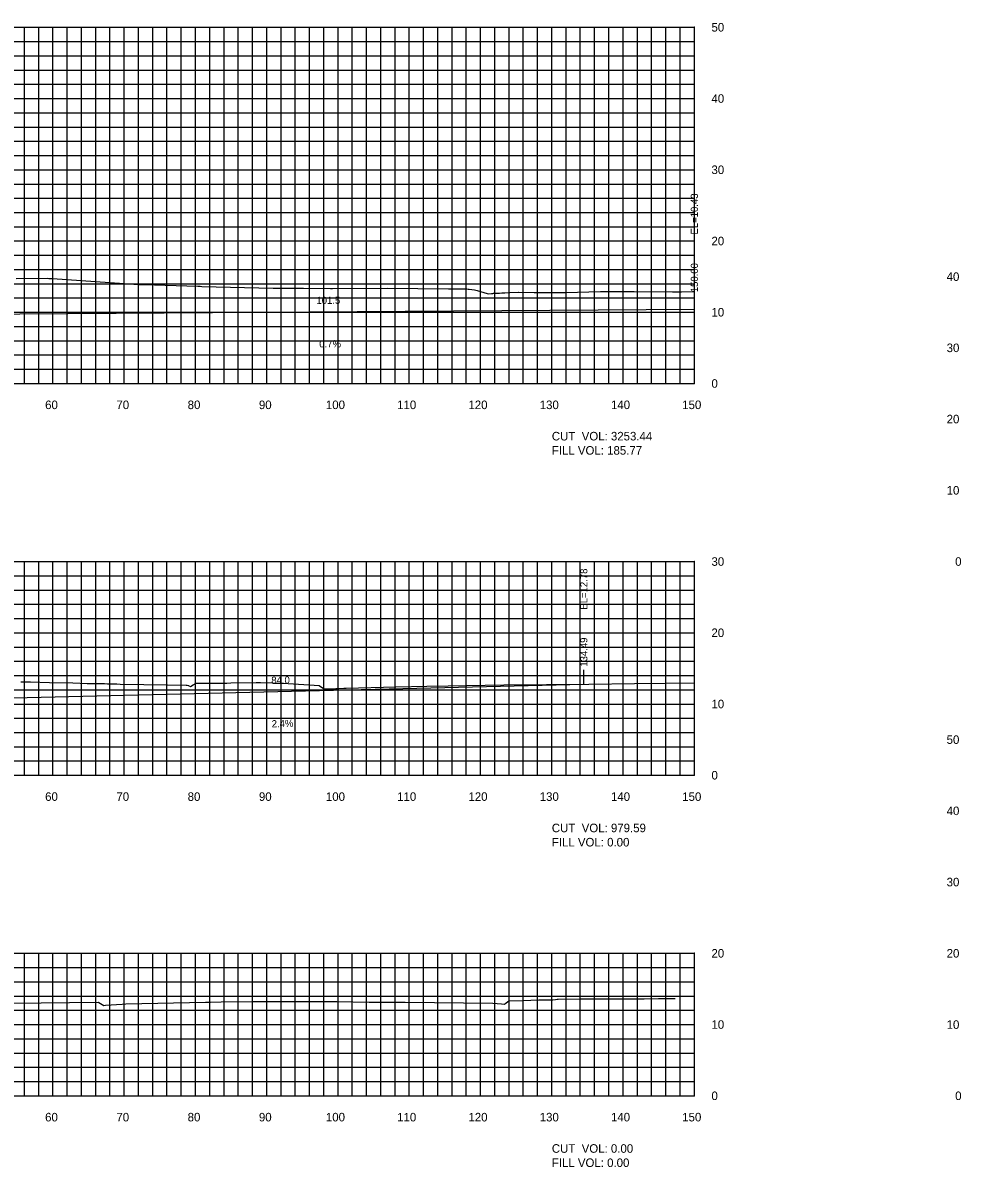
# Model space of a CAD drawing. Extents: x 1797789 to 1803805, y 249066 to 250293.
# Drawn here: x 1802346.8 to 1802478.4, y 250089.4 to 250250 of the extents above; entities that cross this region are included whole.
import ezdxf

# ---------------------------------------------------------------- set-up
doc = ezdxf.new("R2010")
doc.units = 0
for name, color, linetype in [('10', 7, 'Continuous'), ('3', 7, 'Continuous'), ('31', 7, 'Continuous'), ('4', 7, 'Continuous'), ('60', 7, 'Continuous'), ('ANNO-TXT', 7, 'Continuous'), ('CL-CNST', 7, 'Continuous'), ('Level 62', 7, 'Continuous'), ('M-ROADS', 7, 'Continuous')]:
    doc.layers.add(name, color=color, linetype=linetype)

msp = doc.modelspace()

# ---------------------------------------------------------------- linework, layer by layer
for p, q in [((1802441, 250209.87), (1802441, 250211.87)), ((1802425.49, 250157.21), (1802425.49, 250159.21))]:
    msp.add_line(p, q)
at = {"layer": '60'}
for p, q in [((1802441, 250199.43), (1802441, 250249.43)), ((1802441.06, 250249.43), (1802441, 250249.43)), ((1802441.06, 250239.43), (1802441, 250239.43)), ((1802441.06, 250229.43), (1802441, 250229.43)), ((1802441.06, 250219.43), (1802441, 250219.43)), ((1802441.06, 250209.43), (1802441, 250209.43)), ((1802141, 250199.43), (1802441, 250199.43)), ((1802351, 250199.37), (1802351, 250199.43)), ((1802361, 250199.37), (1802361, 250199.43)), ((1802371, 250199.37), (1802371, 250199.43)), ((1802381, 250199.37), (1802381, 250199.43)), ((1802391, 250199.37), (1802391, 250199.43)), ((1802401, 250199.37), (1802401, 250199.43)), ((1802411, 250199.37), (1802411, 250199.43)), ((1802421, 250199.37), (1802421, 250199.43)), ((1802431, 250199.37), (1802431, 250199.43)), ((1802441, 250199.37), (1802441, 250199.43)), ((1802441.06, 250199.43), (1802441, 250199.43)), ((1802441, 250144.43), (1802441, 250174.43)), ((1802441.06, 250174.43), (1802441, 250174.43)), ((1802441.06, 250164.43), (1802441, 250164.43)), ((1802441.06, 250154.43), (1802441, 250154.43)), ((1802141, 250144.43), (1802441, 250144.43)), ((1802351, 250144.37), (1802351, 250144.43)), ((1802361, 250144.37), (1802361, 250144.43)), ((1802371, 250144.37), (1802371, 250144.43)), ((1802381, 250144.37), (1802381, 250144.43)), ((1802391, 250144.37), (1802391, 250144.43)), ((1802401, 250144.37), (1802401, 250144.43)), ((1802411, 250144.37), (1802411, 250144.43)), ((1802421, 250144.37), (1802421, 250144.43)), ((1802431, 250144.37), (1802431, 250144.43)), ((1802441, 250144.37), (1802441, 250144.43)), ((1802441.06, 250144.43), (1802441, 250144.43)), ((1802441, 250099.43), (1802441, 250119.43)), ((1802441.06, 250119.43), (1802441, 250119.43)), ((1802441.06, 250109.43), (1802441, 250109.43)), ((1802141, 250099.43), (1802441, 250099.43)), ((1802351, 250099.37), (1802351, 250099.43)), ((1802361, 250099.37), (1802361, 250099.43)), ((1802371, 250099.37), (1802371, 250099.43)), ((1802381, 250099.37), (1802381, 250099.43)), ((1802391, 250099.37), (1802391, 250099.43)), ((1802401, 250099.37), (1802401, 250099.43)), ((1802411, 250099.37), (1802411, 250099.43)), ((1802421, 250099.37), (1802421, 250099.43)), ((1802431, 250099.37), (1802431, 250099.43)), ((1802441, 250099.37), (1802441, 250099.43)), ((1802441.06, 250099.43), (1802441, 250099.43))]:
    msp.add_line(p, q, dxfattribs=at)
at = {"layer": 'CL-CNST'}
for points in [[(1802182.07, 250229.29), (1802242.5, 250209.15), (1802243.5, 250209.11), (1802250.5, 250209), (1802250.5, 250209), (1802250.83, 250209), (1802251, 250208.5), (1802253, 250208.66), (1802257, 250208.75), (1802291, 250209.5), (1802325, 250208.75), (1802329, 250208.66), (1802331, 250208.5), (1802331.17, 250209), (1802331.5, 250209), (1802331.5, 250209), (1802338.5, 250209.11), (1802339.5, 250209.15), (1802441, 250209.87)], [(1802236.11, 250157.24), (1802242.5, 250155.11), (1802243.5, 250155.07), (1802250.5, 250154.96), (1802250.5, 250154.96), (1802250.83, 250154.96), (1802251, 250154.46), (1802253, 250154.62), (1802257, 250154.71), (1802291, 250155.46), (1802325, 250154.71), (1802329, 250154.62), (1802331, 250154.46), (1802331.17, 250154.96), (1802331.5, 250154.96), (1802333.5, 250155.04), (1802340.5, 250155.15), (1802341.5, 250155.19), (1802425.49, 250157.21)]]:
    msp.add_lwpolyline(points, dxfattribs=at)
at = {"layer": 'Level 62'}
for p, q in [((1802141, 250249.43), (1802441, 250249.43)), ((1802347, 250199.43), (1802347, 250249.43)), ((1802349, 250199.43), (1802349, 250249.43)), ((1802351, 250199.43), (1802351, 250249.43)), ((1802353, 250199.43), (1802353, 250249.43)), ((1802355, 250199.43), (1802355, 250249.43)), ((1802357, 250199.43), (1802357, 250249.43)), ((1802359, 250199.43), (1802359, 250249.43)), ((1802361, 250199.43), (1802361, 250249.43)), ((1802363, 250199.43), (1802363, 250249.43)), ((1802365, 250199.43), (1802365, 250249.43)), ((1802367, 250199.43), (1802367, 250249.43)), ((1802369, 250199.43), (1802369, 250249.43)), ((1802371, 250199.43), (1802371, 250249.43)), ((1802373, 250199.43), (1802373, 250249.43)), ((1802375, 250199.43), (1802375, 250249.43)), ((1802377, 250199.43), (1802377, 250249.43)), ((1802379, 250199.43), (1802379, 250249.43)), ((1802381, 250199.43), (1802381, 250249.43)), ((1802383, 250199.43), (1802383, 250249.43)), ((1802385, 250199.43), (1802385, 250249.43)), ((1802387, 250199.43), (1802387, 250249.43)), ((1802389, 250199.43), (1802389, 250249.43)), ((1802391, 250199.43), (1802391, 250249.43)), ((1802393, 250199.43), (1802393, 250249.43)), ((1802395, 250199.43), (1802395, 250249.43)), ((1802397, 250199.43), (1802397, 250249.43)), ((1802399, 250199.43), (1802399, 250249.43)), ((1802401, 250199.43), (1802401, 250249.43)), ((1802403, 250199.43), (1802403, 250249.43)), ((1802405, 250199.43), (1802405, 250249.43)), ((1802407, 250199.43), (1802407, 250249.43)), ((1802409, 250199.43), (1802409, 250249.43)), ((1802411, 250199.43), (1802411, 250249.43)), ((1802413, 250199.43), (1802413, 250249.43)), ((1802415, 250199.43), (1802415, 250249.43)), ((1802417, 250199.43), (1802417, 250249.43)), ((1802419, 250199.43), (1802419, 250249.43)), ((1802421, 250199.43), (1802421, 250249.43)), ((1802423, 250199.43), (1802423, 250249.43)), ((1802425, 250199.43), (1802425, 250249.43)), ((1802427, 250199.43), (1802427, 250249.43)), ((1802429, 250199.43), (1802429, 250249.43)), ((1802431, 250199.43), (1802431, 250249.43)), ((1802433, 250199.43), (1802433, 250249.43)), ((1802435, 250199.43), (1802435, 250249.43)), ((1802437, 250199.43), (1802437, 250249.43)), ((1802439, 250199.43), (1802439, 250249.43)), ((1802441, 250199.43), (1802441, 250249.43)), ((1802141, 250247.43), (1802441, 250247.43)), ((1802141, 250245.43), (1802441, 250245.43)), ((1802141, 250243.43), (1802441, 250243.43)), ((1802141, 250241.43), (1802441, 250241.43)), ((1802141, 250239.43), (1802441, 250239.43)), ((1802141, 250237.43), (1802441, 250237.43)), ((1802141, 250235.43), (1802441, 250235.43)), ((1802141, 250233.43), (1802441, 250233.43)), ((1802141, 250231.43), (1802441, 250231.43)), ((1802141, 250229.43), (1802441, 250229.43)), ((1802141, 250227.43), (1802441, 250227.43)), ((1802141, 250225.43), (1802441, 250225.43)), ((1802141, 250223.43), (1802441, 250223.43)), ((1802141, 250221.43), (1802441, 250221.43)), ((1802141, 250219.43), (1802441, 250219.43)), ((1802141, 250217.43), (1802441, 250217.43)), ((1802141, 250215.43), (1802441, 250215.43)), ((1802141, 250213.43), (1802441, 250213.43)), ((1802141, 250211.43), (1802441, 250211.43)), ((1802141, 250209.43), (1802441, 250209.43)), ((1802141, 250207.43), (1802441, 250207.43)), ((1802141, 250205.43), (1802441, 250205.43)), ((1802141, 250203.43), (1802441, 250203.43)), ((1802141, 250201.43), (1802441, 250201.43)), ((1802141, 250199.43), (1802441, 250199.43)), ((1802141, 250174.43), (1802441, 250174.43)), ((1802347, 250144.43), (1802347, 250174.43)), ((1802349, 250144.43), (1802349, 250174.43)), ((1802351, 250144.43), (1802351, 250174.43)), ((1802353, 250144.43), (1802353, 250174.43)), ((1802355, 250144.43), (1802355, 250174.43)), ((1802357, 250144.43), (1802357, 250174.43)), ((1802359, 250144.43), (1802359, 250174.43)), ((1802361, 250144.43), (1802361, 250174.43)), ((1802363, 250144.43), (1802363, 250174.43)), ((1802365, 250144.43), (1802365, 250174.43)), ((1802367, 250144.43), (1802367, 250174.43)), ((1802369, 250144.43), (1802369, 250174.43)), ((1802371, 250144.43), (1802371, 250174.43)), ((1802373, 250144.43), (1802373, 250174.43)), ((1802375, 250144.43), (1802375, 250174.43)), ((1802377, 250144.43), (1802377, 250174.43)), ((1802379, 250144.43), (1802379, 250174.43)), ((1802381, 250144.43), (1802381, 250174.43)), ((1802383, 250144.43), (1802383, 250174.43)), ((1802385, 250144.43), (1802385, 250174.43)), ((1802387, 250144.43), (1802387, 250174.43)), ((1802389, 250144.43), (1802389, 250174.43)), ((1802391, 250144.43), (1802391, 250174.43)), ((1802393, 250144.43), (1802393, 250174.43)), ((1802395, 250144.43), (1802395, 250174.43)), ((1802397, 250144.43), (1802397, 250174.43)), ((1802399, 250144.43), (1802399, 250174.43)), ((1802401, 250144.43), (1802401, 250174.43)), ((1802403, 250144.43), (1802403, 250174.43)), ((1802405, 250144.43), (1802405, 250174.43)), ((1802407, 250144.43), (1802407, 250174.43)), ((1802409, 250144.43), (1802409, 250174.43)), ((1802411, 250144.43), (1802411, 250174.43)), ((1802413, 250144.43), (1802413, 250174.43)), ((1802415, 250144.43), (1802415, 250174.43)), ((1802417, 250144.43), (1802417, 250174.43)), ((1802419, 250144.43), (1802419, 250174.43)), ((1802421, 250144.43), (1802421, 250174.43)), ((1802423, 250144.43), (1802423, 250174.43)), ((1802425, 250144.43), (1802425, 250174.43)), ((1802427, 250144.43), (1802427, 250174.43)), ((1802429, 250144.43), (1802429, 250174.43)), ((1802431, 250144.43), (1802431, 250174.43)), ((1802433, 250144.43), (1802433, 250174.43)), ((1802435, 250144.43), (1802435, 250174.43)), ((1802437, 250144.43), (1802437, 250174.43)), ((1802439, 250144.43), (1802439, 250174.43)), ((1802441, 250144.43), (1802441, 250174.43)), ((1802141, 250172.43), (1802441, 250172.43)), ((1802141, 250170.43), (1802441, 250170.43)), ((1802141, 250168.43), (1802441, 250168.43)), ((1802141, 250166.43), (1802441, 250166.43)), ((1802141, 250164.43), (1802441, 250164.43)), ((1802141, 250162.43), (1802441, 250162.43)), ((1802141, 250160.43), (1802441, 250160.43)), ((1802141, 250158.43), (1802441, 250158.43)), ((1802141, 250156.43), (1802441, 250156.43)), ((1802141, 250154.43), (1802441, 250154.43)), ((1802141, 250152.43), (1802441, 250152.43)), ((1802141, 250150.43), (1802441, 250150.43)), ((1802141, 250148.43), (1802441, 250148.43)), ((1802141, 250146.43), (1802441, 250146.43)), ((1802141, 250144.43), (1802441, 250144.43)), ((1802141, 250119.43), (1802441, 250119.43)), ((1802347, 250099.43), (1802347, 250119.43)), ((1802349, 250099.43), (1802349, 250119.43)), ((1802351, 250099.43), (1802351, 250119.43)), ((1802353, 250099.43), (1802353, 250119.43)), ((1802355, 250099.43), (1802355, 250119.43)), ((1802357, 250099.43), (1802357, 250119.43)), ((1802359, 250099.43), (1802359, 250119.43)), ((1802361, 250099.43), (1802361, 250119.43)), ((1802363, 250099.43), (1802363, 250119.43)), ((1802365, 250099.43), (1802365, 250119.43)), ((1802367, 250099.43), (1802367, 250119.43)), ((1802369, 250099.43), (1802369, 250119.43)), ((1802371, 250099.43), (1802371, 250119.43)), ((1802373, 250099.43), (1802373, 250119.43)), ((1802375, 250099.43), (1802375, 250119.43)), ((1802377, 250099.43), (1802377, 250119.43)), ((1802379, 250099.43), (1802379, 250119.43)), ((1802381, 250099.43), (1802381, 250119.43)), ((1802383, 250099.43), (1802383, 250119.43)), ((1802385, 250099.43), (1802385, 250119.43)), ((1802387, 250099.43), (1802387, 250119.43)), ((1802389, 250099.43), (1802389, 250119.43)), ((1802391, 250099.43), (1802391, 250119.43)), ((1802393, 250099.43), (1802393, 250119.43)), ((1802395, 250099.43), (1802395, 250119.43)), ((1802397, 250099.43), (1802397, 250119.43)), ((1802399, 250099.43), (1802399, 250119.43)), ((1802401, 250099.43), (1802401, 250119.43)), ((1802403, 250099.43), (1802403, 250119.43)), ((1802405, 250099.43), (1802405, 250119.43)), ((1802407, 250099.43), (1802407, 250119.43)), ((1802409, 250099.43), (1802409, 250119.43)), ((1802411, 250099.43), (1802411, 250119.43)), ((1802413, 250099.43), (1802413, 250119.43)), ((1802415, 250099.43), (1802415, 250119.43)), ((1802417, 250099.43), (1802417, 250119.43)), ((1802419, 250099.43), (1802419, 250119.43)), ((1802421, 250099.43), (1802421, 250119.43)), ((1802423, 250099.43), (1802423, 250119.43)), ((1802425, 250099.43), (1802425, 250119.43)), ((1802427, 250099.43), (1802427, 250119.43)), ((1802429, 250099.43), (1802429, 250119.43)), ((1802431, 250099.43), (1802431, 250119.43)), ((1802433, 250099.43), (1802433, 250119.43)), ((1802435, 250099.43), (1802435, 250119.43)), ((1802437, 250099.43), (1802437, 250119.43)), ((1802439, 250099.43), (1802439, 250119.43)), ((1802441, 250099.43), (1802441, 250119.43)), ((1802141, 250117.43), (1802441, 250117.43)), ((1802141, 250115.43), (1802441, 250115.43)), ((1802141, 250113.43), (1802441, 250113.43)), ((1802141, 250111.43), (1802441, 250111.43)), ((1802141, 250109.43), (1802441, 250109.43)), ((1802141, 250107.43), (1802441, 250107.43)), ((1802141, 250105.43), (1802441, 250105.43)), ((1802141, 250103.43), (1802441, 250103.43)), ((1802141, 250101.43), (1802441, 250101.43)), ((1802141, 250099.43), (1802441, 250099.43))]:
    msp.add_line(p, q, dxfattribs=at)
at = {"layer": 'M-ROADS'}
for points in [[(1802345.82, 250214.15), (1802350.23, 250214.19), (1802350.43, 250214.18), (1802350.94, 250214.15), (1802363, 250213.32), (1802363.39, 250213.32), (1802363.71, 250213.33), (1802371.32, 250213.08), (1802371.64, 250213.07), (1802371.9, 250213.06), (1802381.92, 250212.8), (1802382.26, 250212.8), (1802383.07, 250212.8), (1802385.82, 250212.79), (1802386.17, 250212.79), (1802389.95, 250212.77), (1802390.24, 250212.77), (1802397.89, 250212.83), (1802406.52, 250212.72), (1802406.53, 250212.72), (1802406.54, 250212.72), (1802406.89, 250212.72), (1802407.13, 250212.72), (1802407.92, 250212.72), (1802408.05, 250212.72), (1802408.09, 250212.72), (1802408.12, 250212.72), (1802408.93, 250212.72), (1802409.06, 250212.72), (1802409.24, 250212.69), (1802409.42, 250212.68), (1802410.15, 250212.56), (1802410.53, 250212.46), (1802411.93, 250212.04), (1802412.05, 250212), (1802412.55, 250212.05), (1802412.58, 250212.06), (1802412.62, 250212.06), (1802412.65, 250212.07), (1802412.7, 250212.07), (1802412.74, 250212.08), (1802412.8, 250212.09), (1802412.81, 250212.09), (1802412.88, 250212.09), (1802412.98, 250212.09), (1802413.09, 250212.1), (1802413.24, 250212.1), (1802413.42, 250212.11), (1802413.65, 250212.12), (1802413.97, 250212.13), (1802414.42, 250212.15), (1802415.11, 250212.18), (1802416.29, 250212.23), (1802416.32, 250212.23), (1802418.51, 250212.22), (1802418.71, 250212.22), (1802420.73, 250212.22), (1802421.13, 250212.22), (1802422.95, 250212.22), (1802427.83, 250212.34), (1802428.17, 250212.34), (1802428.58, 250212.34), (1802429.09, 250212.34), (1802429.25, 250212.34), (1802429.68, 250212.34), (1802430.23, 250212.34), (1802431.19, 250212.34), (1802432.55, 250212.34), (1802437.95, 250212.3), (1802439.21, 250212.31), (1802440.83, 250212.33), (1802441, 250212.33)], [(1802346.47, 250157.56), (1802347.09, 250157.55), (1802347.87, 250157.52), (1802350.53, 250157.46), (1802353.78, 250157.38), (1802355.82, 250157.32), (1802355.93, 250157.32), (1802357.21, 250157.3), (1802358.22, 250157.29), (1802358.63, 250157.28), (1802359.08, 250157.27), (1802359.38, 250157.26), (1802359.97, 250157.24), (1802360.44, 250157.23), (1802367.05, 250157.13), (1802367.07, 250157.13), (1802369.69, 250157.08), (1802369.71, 250157.08), (1802369.82, 250157.08), (1802369.83, 250157.07), (1802370, 250157.01), (1802370.08, 250156.97), (1802370.28, 250156.88), (1802370.66, 250157.12), (1802371.08, 250157.34), (1802373.81, 250157.37), (1802373.96, 250157.37), (1802375.39, 250157.35), (1802375.94, 250157.38), (1802379.52, 250157.46), (1802379.81, 250157.46), (1802380.11, 250157.46), (1802381.76, 250157.38), (1802382.1, 250157.36), (1802383.31, 250157.34), (1802388.36, 250157.01), (1802388.97, 250156.62), (1802389.08, 250156.54), (1802389.1, 250156.55), (1802390.71, 250156.62), (1802390.86, 250156.6), (1802391.13, 250156.61), (1802391.81, 250156.65), (1802392.13, 250156.67), (1802399.11, 250156.82), (1802403.45, 250156.93), (1802406.47, 250156.99), (1802414.28, 250157.12), (1802426.21, 250157.22), (1802432.62, 250157.31), (1802437.03, 250157.35), (1802441, 250157.4)], [(1802345.31, 250112.42), (1802357.33, 250112.57), (1802357.44, 250112.51), (1802358.12, 250112.12), (1802358.37, 250112.13), (1802360.71, 250112.3), (1802361.24, 250112.32), (1802372.41, 250112.59), (1802373.09, 250112.59), (1802374.59, 250112.61), (1802379.09, 250112.65), (1802379.87, 250112.66), (1802390.32, 250112.66), (1802390.83, 250112.66), (1802395.37, 250112.59), (1802400.4, 250112.55), (1802412.72, 250112.44), (1802413.94, 250112.33), (1802414.36, 250112.28), (1802414.6, 250112.47), (1802414.96, 250112.74), (1802416.95, 250112.8), (1802419.2, 250112.88), (1802420.17, 250112.91), (1802421.12, 250112.92), (1802421.5, 250112.96), (1802421.73, 250112.97), (1802421.9, 250112.97), (1802425.09, 250113.04), (1802427.69, 250113.05), (1802429.99, 250113.03), (1802431.39, 250113.02), (1802432.28, 250113.02), (1802433.95, 250113.03), (1802435.96, 250113.07), (1802436.91, 250113.09), (1802438.31, 250113.1)]]:
    msp.add_lwpolyline(points, dxfattribs=at)

# ---------------------------------------------------------------- texts
at = {"layer": '10'}
for s, p in [('60', (1802349.9, 250195.83)), ('70', (1802359.9, 250195.83)), ('80', (1802369.9, 250195.83)), ('90', (1802379.9, 250195.83)), ('100', (1802389.3, 250195.83)), ('110', (1802399.3, 250195.83)), ('120', (1802409.3, 250195.83)), ('130', (1802419.3, 250195.83)), ('140', (1802429.3, 250195.83)), ('150', (1802439.3, 250195.83)), ('60', (1802349.9, 250140.83)), ('70', (1802359.9, 250140.83)), ('80', (1802369.9, 250140.83)), ('90', (1802379.9, 250140.83)), ('100', (1802389.3, 250140.83)), ('110', (1802399.3, 250140.83)), ('120', (1802409.3, 250140.83)), ('130', (1802419.3, 250140.83)), ('140', (1802429.3, 250140.83)), ('150', (1802439.3, 250140.83)), ('60', (1802349.9, 250095.83)), ('70', (1802359.9, 250095.83)), ('80', (1802369.9, 250095.83)), ('90', (1802379.9, 250095.83)), ('100', (1802389.3, 250095.83)), ('110', (1802399.3, 250095.83)), ('120', (1802409.3, 250095.83)), ('130', (1802419.3, 250095.83)), ('140', (1802429.3, 250095.83)), ('150', (1802439.3, 250095.83))]:
    msp.add_text(s, height=1.2, dxfattribs=at).set_placement(p)
at = {"layer": '3'}
for s, p in [('EL=10.43', (1802441.5, 250220.34)), ('150.00', (1802441.5, 250212.24)), ('EL=12.78', (1802425.99, 250167.68)), ('134.49', (1802425.99, 250159.67))]:
    msp.add_text(s, height=1, rotation=90, dxfattribs=at).set_placement(p)
at = {"layer": '31'}
for s, p in [('50', (1802443.4, 250248.83)), ('40', (1802443.4, 250238.83)), ('30', (1802443.4, 250228.83)), ('20', (1802443.4, 250218.83)), ('40', (1802476.4, 250213.83)), ('10', (1802443.4, 250208.83)), ('30', (1802476.4, 250203.83)), ('0', (1802443.4, 250198.83)), ('20', (1802476.4, 250193.83)), ('10', (1802476.4, 250183.83)), ('30', (1802443.4, 250173.83)), ('0', (1802477.6, 250173.83)), ('20', (1802443.4, 250163.83)), ('10', (1802443.4, 250153.83)), ('50', (1802476.4, 250148.83)), ('0', (1802443.4, 250143.83)), ('40', (1802476.4, 250138.83)), ('30', (1802476.4, 250128.83)), ('20', (1802443.4, 250118.83)), ('20', (1802476.4, 250118.83)), ('10', (1802443.4, 250108.83)), ('10', (1802476.4, 250108.83)), ('0', (1802443.4, 250098.83)), ('0', (1802477.6, 250098.83))]:
    msp.add_text(s, height=1.2, dxfattribs=at).set_placement(p)
at = {"layer": '4'}
for s, rotation, p in [('101.5', 0.4051, (1802387.97, 250210.59)), ('0.7%', 0.4051, (1802388.37, 250204.49)), ('84.0', 1.3814, (1802381.65, 250157.25)), ('2.4%', 1.3814, (1802381.7, 250151.15))]:
    msp.add_text(s, height=1, rotation=rotation, dxfattribs=at).set_placement(p)
at = {"layer": 'ANNO-TXT'}
for s, p in [('CUT  VOL: 3253.44', (1802421, 250191.43)), ('FILL VOL: 185.77', (1802421, 250189.43)), ('CUT  VOL: 979.59', (1802421, 250136.43)), ('FILL VOL: 0.00', (1802421, 250134.43)), ('CUT  VOL: 0.00', (1802421, 250091.43)), ('FILL VOL: 0.00', (1802421, 250089.43))]:
    msp.add_text(s, height=1.2, dxfattribs=at).set_placement(p)

doc.saveas('drawing.dxf')
